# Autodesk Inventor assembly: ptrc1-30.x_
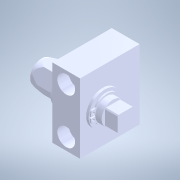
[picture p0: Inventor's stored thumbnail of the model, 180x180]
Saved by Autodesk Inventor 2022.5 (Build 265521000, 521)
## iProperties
Created: 2023-04
Part Number: ptrc1-30.x_
Document SubType Name: Assembly
Designer: ImaoCorp
Sending System: SOLIDWORKS 2021-2021301
MC: AMD64
MC_MODEL: Intel64 Family 6 Model 60 Stepping 3, GenuineIntel
OS: Windows_NT
FRU: Parasolid Version 32.1, build 255,  1- 1-2021
FORMAT: text
GUISE: transmit
KEY: ptrc1-30
FILE: ptrc1-30.x_t
DATE: Fri Apr  7 10:54:38 2023
Author: ImaoCorp
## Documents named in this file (3)
- X:\14_SW2022-Inv2022\00_全2023-1023新製品(TCC)まで\p\ptrc1-30\PTRC1-30.iam
- X:\14_SW2022-Inv2022\00_全2023-1023新製品(TCC)まで\p\ptrc1-30\ptrc1-30_01.ipt
- X:\14_SW2022-Inv2022\00_全2023-1023新製品(TCC)まで\p\ptrc1-30\ptrc1-30_02.ipt
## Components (2 placed, 2 different names)
1. ptrc1-30_01
2. ptrc1-30_02
